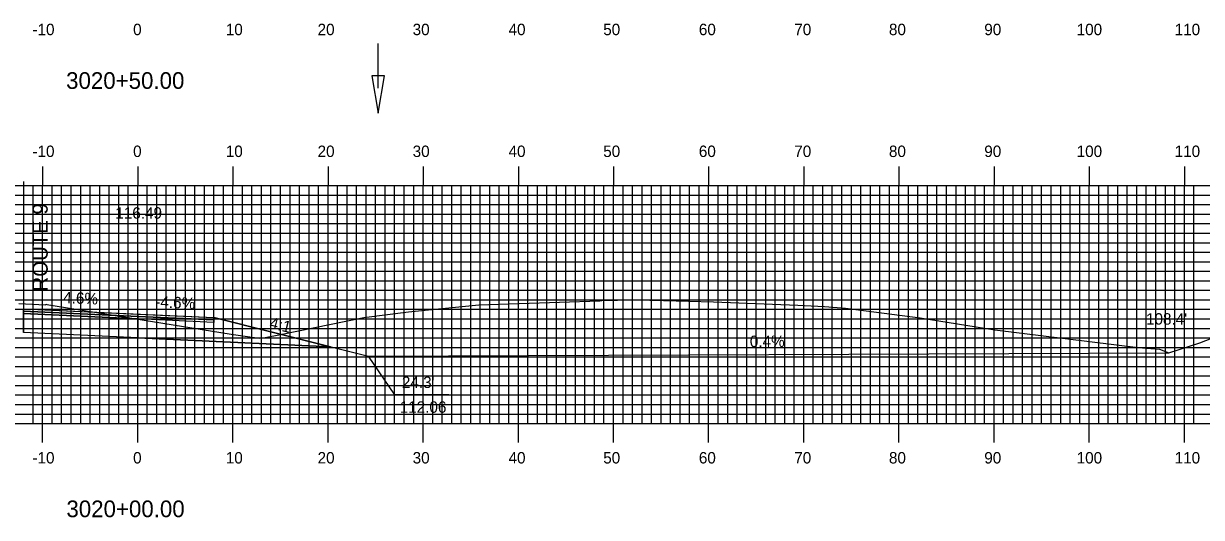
# Model space of a CAD drawing. Extents: x 1685979 to 1686323, y 461260 to 461480.
# Drawn here: x 1686133.3 to 1686257.1, y 461358.2 to 461410.1 of the extents above; entities that cross this region are included whole.
import ezdxf

# ---------------------------------------------------------------- set-up
doc = ezdxf.new("R2010")
doc.units = 0
for name, color, linetype in [('ANNOTATION', 7, 'Continuous'), ('D_Drainage_Ditch_Line', 7, 'Continuous'), ('D_Roadway_Centerline_Text', 7, 'Continuous'), ('D_Roadway_Edge_Shoulder', 7, 'Continuous'), ('D_Roadway_Edge_TW', 7, 'Continuous'), ('D_Roadway_Pavement', 7, 'Continuous'), ('D_Roadway_SlopeLines', 7, 'Continuous'), ('D_Roadway_SubGrade', 7, 'Continuous'), ('D_Text_Standard', 7, 'Continuous'), ('H_V ANNOTATION', 7, 'Continuous'), ('M_Roadway_Centerline', 7, 'Continuous'), ('MAJOR', 7, 'Continuous'), ('MINOR', 7, 'Continuous'), ('S_Roadway_Centerline', 7, 'Continuous')]:
    doc.layers.add(name, color=color, linetype=linetype)

msp = doc.modelspace()

# ---------------------------------------------------------------- linework, layer by layer
at = {"layer": 'ANNOTATION'}
msp.add_lwpolyline([(1686177.97, 461371.08), (1686172.28, 461371.08), (1686169.51, 461375.13)], dxfattribs=at)
at = {"layer": 'D_Drainage_Ditch_Line'}
msp.add_line((1686170.53, 461403.29), (1686170.53, 461407.99), dxfattribs=at)
msp.add_lwpolyline([(1686171.18, 461404.6), (1686169.87, 461404.6), (1686170.53, 461400.66)], close=True, dxfattribs=at)
at = {"layer": 'D_Roadway_Edge_Shoulder'}
for points in [[(1686133.26, 461379.87), (1686133.26, 461380.12), (1686153.26, 461379.2), (1686153.26, 461378.95), (1686145.26, 461379.31)], [(1686145.26, 461379.56), (1686153.26, 461379.2), (1686153.26, 461378.95), (1686145.26, 461379.31)], [(1686145.26, 461379.56), (1686153.26, 461379.2), (1686153.26, 461378.95), (1686145.26, 461379.31)], [(1686145.26, 461379.56), (1686153.26, 461379.2), (1686153.26, 461378.95), (1686145.26, 461379.31)], [(1686145.26, 461379.31), (1686153.26, 461378.95), (1686153.26, 461378.7), (1686145.26, 461379.06)]]:
    msp.add_lwpolyline(points, close=True, dxfattribs=at)
at = {"layer": 'D_Roadway_Edge_TW'}
msp.add_lwpolyline([(1686133.26, 461380.12), (1686145.26, 461379.56), (1686145.26, 461379.31), (1686133.26, 461379.87)], close=True, dxfattribs=at)
msp.add_lwpolyline([(1686133.26, 461380.12), (1686145.26, 461379.56), (1686145.26, 461379.31), (1686133.26, 461379.87)], close=True, dxfattribs=at)
msp.add_lwpolyline([(1686133.26, 461380.12), (1686145.26, 461379.56), (1686145.26, 461379.31), (1686133.26, 461379.87)], close=True, dxfattribs=at)
for points in [[(1686133.26, 461380.12), (1686133.26, 461379.87)], [(1686145.26, 461379.31), (1686145.26, 461379.56)]]:
    msp.add_lwpolyline(points, dxfattribs=at)
at = {"layer": 'D_Roadway_Pavement'}
msp.add_lwpolyline([(1686133.26, 461379.87), (1686145.26, 461379.31), (1686145.26, 461379.06), (1686133.26, 461379.62)], close=True, dxfattribs=at)
msp.add_lwpolyline([(1686133.26, 461379.87), (1686145.26, 461379.31), (1686145.26, 461379.06), (1686133.26, 461379.62)], close=True, dxfattribs=at)
msp.add_lwpolyline([(1686133.26, 461379.87), (1686145.26, 461379.31), (1686145.26, 461379.06), (1686133.26, 461379.62)], close=True, dxfattribs=at)
msp.add_lwpolyline([(1686133.26, 461379.87), (1686145.26, 461379.31), (1686145.26, 461379.06), (1686133.26, 461379.62)], close=True, dxfattribs=at)
msp.add_lwpolyline([(1686133.26, 461379.87), (1686145.26, 461379.31), (1686145.26, 461379.06), (1686133.26, 461379.62)], close=True, dxfattribs=at)
for points in [[(1686133.26, 461379.87), (1686133.26, 461379.62)], [(1686145.26, 461379.31), (1686145.26, 461379.06)], [(1686145.26, 461379.31), (1686145.26, 461379.06)], [(1686145.26, 461379.31), (1686145.26, 461379.06)], [(1686145.26, 461379.31), (1686145.26, 461379.06)], [(1686145.26, 461379.31), (1686145.26, 461379.06)], [(1686145.26, 461379.31), (1686145.26, 461379.06)], [(1686145.26, 461379.06), (1686145.26, 461379.31)], [(1686145.26, 461379.31), (1686145.26, 461379.06)]]:
    msp.add_lwpolyline(points, dxfattribs=at)
at = {"layer": 'D_Roadway_SlopeLines'}
for points in [[(1686153.26, 461379.2), (1686169.51, 461375.13)], [(1686153.26, 461379.2), (1686169.51, 461375.13)], [(1686153.26, 461379.2), (1686169.51, 461375.13)], [(1686153.26, 461379.2), (1686169.51, 461375.13)], [(1686169.51, 461375.13), (1686253.62, 461375.48)], [(1686169.51, 461375.13), (1686253.62, 461375.48)], [(1686169.51, 461375.13), (1686253.62, 461375.48)], [(1686169.51, 461375.13), (1686253.62, 461375.48)]]:
    msp.add_lwpolyline(points, dxfattribs=at)
at = {"layer": 'D_Roadway_SubGrade'}
msp.add_line((1686133.26, 461393.49), (1686133.26, 461377.62), dxfattribs=at)
msp.add_lwpolyline([(1686133.26, 461379.62), (1686133.26, 461377.62)], dxfattribs=at)
msp.add_lwpolyline([(1686133.26, 461379.62), (1686133.26, 461377.62)], dxfattribs=at)
for points in [[(1686133.26, 461379.62), (1686145.26, 461379.06), (1686145.26, 461377.06), (1686133.26, 461377.62)], [(1686133.26, 461379.62), (1686145.26, 461379.06), (1686145.26, 461377.06), (1686133.26, 461377.62)], [(1686133.26, 461379.62), (1686145.26, 461379.06), (1686145.26, 461377.06), (1686133.26, 461377.62)], [(1686145.26, 461377.06), (1686165.51, 461376.13), (1686153.26, 461379.2), (1686153.26, 461378.95), (1686145.26, 461379.31), (1686145.26, 461379.06)], [(1686145.26, 461379.06), (1686145.26, 461379.31), (1686153.26, 461378.95), (1686153.26, 461379.2), (1686165.51, 461376.13), (1686145.26, 461377.06)], [(1686145.26, 461379.06), (1686145.26, 461379.31), (1686153.26, 461378.95), (1686153.26, 461379.2), (1686165.51, 461376.13), (1686145.26, 461377.06)], [(1686145.26, 461377.06), (1686165.51, 461376.13), (1686153.26, 461379.2), (1686153.26, 461378.95), (1686145.26, 461379.31), (1686145.26, 461379.06)]]:
    msp.add_lwpolyline(points, close=True, dxfattribs=at)
at = {"layer": 'MAJOR'}
for p, q in [((1686135.26, 461395.08), (1686135.26, 461393.07)), ((1686145.26, 461395.08), (1686145.26, 461393.07)), ((1686155.26, 461395.08), (1686155.26, 461393.07)), ((1686165.26, 461395.08), (1686165.26, 461393.07)), ((1686175.26, 461395.08), (1686175.26, 461393.07)), ((1686185.26, 461395.08), (1686185.26, 461393.07)), ((1686195.26, 461395.08), (1686195.26, 461393.07)), ((1686205.26, 461395.08), (1686205.26, 461393.07)), ((1686215.26, 461395.08), (1686215.26, 461393.07)), ((1686225.26, 461395.08), (1686225.26, 461393.07)), ((1686235.26, 461395.08), (1686235.26, 461393.07)), ((1686245.26, 461395.08), (1686245.26, 461393.07)), ((1686255.26, 461395.08), (1686255.26, 461393.07)), ((1686005.26, 461393.07), (1686285.26, 461393.07)), ((1686005.26, 461393.07), (1686285.26, 461393.07)), ((1686135.26, 461368.07), (1686135.26, 461393.07)), ((1686145.26, 461368.07), (1686145.26, 461393.07)), ((1686155.26, 461368.07), (1686155.26, 461393.07)), ((1686165.26, 461368.07), (1686165.26, 461393.07)), ((1686175.26, 461368.07), (1686175.26, 461393.07)), ((1686185.26, 461368.07), (1686185.26, 461393.07)), ((1686195.26, 461368.07), (1686195.26, 461393.07)), ((1686205.26, 461368.07), (1686205.26, 461393.07)), ((1686215.26, 461368.07), (1686215.26, 461393.07)), ((1686225.26, 461368.07), (1686225.26, 461393.07)), ((1686235.26, 461368.07), (1686235.26, 461393.07)), ((1686245.26, 461368.07), (1686245.26, 461393.07)), ((1686255.26, 461368.07), (1686255.26, 461393.07)), ((1686005.26, 461388.07), (1686285.26, 461388.07)), ((1686005.26, 461383.07), (1686285.26, 461383.07)), ((1686005.26, 461378.07), (1686285.26, 461378.07)), ((1686005.26, 461373.07), (1686285.26, 461373.07)), ((1686005.26, 461368.07), (1686285.26, 461368.07)), ((1686005.26, 461368.07), (1686285.26, 461368.07)), ((1686135.26, 461366.07), (1686135.26, 461368.07)), ((1686145.26, 461366.07), (1686145.26, 461368.07)), ((1686155.26, 461366.07), (1686155.26, 461368.07)), ((1686165.26, 461366.07), (1686165.26, 461368.07)), ((1686175.26, 461366.07), (1686175.26, 461368.07)), ((1686185.26, 461366.07), (1686185.26, 461368.07)), ((1686195.26, 461366.07), (1686195.26, 461368.07)), ((1686205.26, 461366.07), (1686205.26, 461368.07)), ((1686215.26, 461366.07), (1686215.26, 461368.07)), ((1686225.26, 461366.07), (1686225.26, 461368.07)), ((1686235.26, 461366.07), (1686235.26, 461368.07)), ((1686245.26, 461366.07), (1686245.26, 461368.07)), ((1686255.26, 461366.07), (1686255.26, 461368.07))]:
    msp.add_line(p, q, dxfattribs=at)
at = {"layer": 'MINOR'}
for p, q in [((1686134.26, 461368.07), (1686134.26, 461393.07)), ((1686136.26, 461368.07), (1686136.26, 461393.07)), ((1686137.26, 461368.07), (1686137.26, 461393.07)), ((1686138.26, 461368.07), (1686138.26, 461393.07)), ((1686139.26, 461368.07), (1686139.26, 461393.07)), ((1686140.26, 461368.07), (1686140.26, 461393.07)), ((1686141.26, 461368.07), (1686141.26, 461393.07)), ((1686142.26, 461368.07), (1686142.26, 461393.07)), ((1686143.26, 461368.07), (1686143.26, 461393.07)), ((1686144.26, 461368.07), (1686144.26, 461393.07)), ((1686146.26, 461368.07), (1686146.26, 461393.07)), ((1686147.26, 461368.07), (1686147.26, 461393.07)), ((1686148.26, 461368.07), (1686148.26, 461393.07)), ((1686149.26, 461368.07), (1686149.26, 461393.07)), ((1686150.26, 461368.07), (1686150.26, 461393.07)), ((1686151.26, 461368.07), (1686151.26, 461393.07)), ((1686152.26, 461368.07), (1686152.26, 461393.07)), ((1686153.26, 461368.07), (1686153.26, 461393.07)), ((1686154.26, 461368.07), (1686154.26, 461393.07)), ((1686156.26, 461368.07), (1686156.26, 461393.07)), ((1686157.26, 461368.07), (1686157.26, 461393.07)), ((1686158.26, 461368.07), (1686158.26, 461393.07)), ((1686159.26, 461368.07), (1686159.26, 461393.07)), ((1686160.26, 461368.07), (1686160.26, 461393.07)), ((1686161.26, 461368.07), (1686161.26, 461393.07)), ((1686162.26, 461368.07), (1686162.26, 461393.07)), ((1686163.26, 461368.07), (1686163.26, 461393.07)), ((1686164.26, 461368.07), (1686164.26, 461393.07)), ((1686166.26, 461368.07), (1686166.26, 461393.07)), ((1686167.26, 461368.07), (1686167.26, 461393.07)), ((1686168.26, 461368.07), (1686168.26, 461393.07)), ((1686169.26, 461368.07), (1686169.26, 461393.07)), ((1686170.26, 461368.07), (1686170.26, 461393.07)), ((1686171.26, 461368.07), (1686171.26, 461393.07)), ((1686172.26, 461368.07), (1686172.26, 461393.07)), ((1686173.26, 461368.07), (1686173.26, 461393.07)), ((1686174.26, 461368.07), (1686174.26, 461393.07)), ((1686176.26, 461368.07), (1686176.26, 461393.07)), ((1686177.26, 461368.07), (1686177.26, 461393.07)), ((1686178.26, 461368.07), (1686178.26, 461393.07)), ((1686179.26, 461368.07), (1686179.26, 461393.07)), ((1686180.26, 461368.07), (1686180.26, 461393.07)), ((1686181.26, 461368.07), (1686181.26, 461393.07)), ((1686182.26, 461368.07), (1686182.26, 461393.07)), ((1686183.26, 461368.07), (1686183.26, 461393.07)), ((1686184.26, 461368.07), (1686184.26, 461393.07)), ((1686186.26, 461368.07), (1686186.26, 461393.07)), ((1686187.26, 461368.07), (1686187.26, 461393.07)), ((1686188.26, 461368.07), (1686188.26, 461393.07)), ((1686189.26, 461368.07), (1686189.26, 461393.07)), ((1686190.26, 461368.07), (1686190.26, 461393.07)), ((1686191.26, 461368.07), (1686191.26, 461393.07)), ((1686192.26, 461368.07), (1686192.26, 461393.07)), ((1686193.26, 461368.07), (1686193.26, 461393.07)), ((1686194.26, 461368.07), (1686194.26, 461393.07)), ((1686196.26, 461368.07), (1686196.26, 461393.07)), ((1686197.26, 461368.07), (1686197.26, 461393.07)), ((1686198.26, 461368.07), (1686198.26, 461393.07)), ((1686199.26, 461368.07), (1686199.26, 461393.07)), ((1686200.26, 461368.07), (1686200.26, 461393.07)), ((1686201.26, 461368.07), (1686201.26, 461393.07)), ((1686202.26, 461368.07), (1686202.26, 461393.07)), ((1686203.26, 461368.07), (1686203.26, 461393.07)), ((1686204.26, 461368.07), (1686204.26, 461393.07)), ((1686206.26, 461368.07), (1686206.26, 461393.07)), ((1686207.26, 461368.07), (1686207.26, 461393.07)), ((1686208.26, 461368.07), (1686208.26, 461393.07)), ((1686209.26, 461368.07), (1686209.26, 461393.07)), ((1686210.26, 461368.07), (1686210.26, 461393.07)), ((1686211.26, 461368.07), (1686211.26, 461393.07)), ((1686212.26, 461368.07), (1686212.26, 461393.07)), ((1686213.26, 461368.07), (1686213.26, 461393.07)), ((1686214.26, 461368.07), (1686214.26, 461393.07)), ((1686216.26, 461368.07), (1686216.26, 461393.07)), ((1686217.26, 461368.07), (1686217.26, 461393.07)), ((1686218.26, 461368.07), (1686218.26, 461393.07)), ((1686219.26, 461368.07), (1686219.26, 461393.07)), ((1686220.26, 461368.07), (1686220.26, 461393.07)), ((1686221.26, 461368.07), (1686221.26, 461393.07)), ((1686222.26, 461368.07), (1686222.26, 461393.07)), ((1686223.26, 461368.07), (1686223.26, 461393.07)), ((1686224.26, 461368.07), (1686224.26, 461393.07)), ((1686226.26, 461368.07), (1686226.26, 461393.07)), ((1686227.26, 461368.07), (1686227.26, 461393.07)), ((1686228.26, 461368.07), (1686228.26, 461393.07)), ((1686229.26, 461368.07), (1686229.26, 461393.07)), ((1686230.26, 461368.07), (1686230.26, 461393.07)), ((1686231.26, 461368.07), (1686231.26, 461393.07)), ((1686232.26, 461368.07), (1686232.26, 461393.07)), ((1686233.26, 461368.07), (1686233.26, 461393.07)), ((1686234.26, 461368.07), (1686234.26, 461393.07)), ((1686236.26, 461368.07), (1686236.26, 461393.07)), ((1686237.26, 461368.07), (1686237.26, 461393.07)), ((1686238.26, 461368.07), (1686238.26, 461393.07)), ((1686239.26, 461368.07), (1686239.26, 461393.07)), ((1686240.26, 461368.07), (1686240.26, 461393.07)), ((1686241.26, 461368.07), (1686241.26, 461393.07)), ((1686242.26, 461368.07), (1686242.26, 461393.07)), ((1686243.26, 461368.07), (1686243.26, 461393.07)), ((1686244.26, 461368.07), (1686244.26, 461393.07)), ((1686246.26, 461368.07), (1686246.26, 461393.07)), ((1686247.26, 461368.07), (1686247.26, 461393.07)), ((1686248.26, 461368.07), (1686248.26, 461393.07)), ((1686249.26, 461368.07), (1686249.26, 461393.07)), ((1686250.26, 461368.07), (1686250.26, 461393.07)), ((1686251.26, 461368.07), (1686251.26, 461393.07)), ((1686252.26, 461368.07), (1686252.26, 461393.07)), ((1686253.26, 461368.07), (1686253.26, 461393.07)), ((1686254.26, 461368.07), (1686254.26, 461393.07)), ((1686256.26, 461368.07), (1686256.26, 461393.07)), ((1686005.26, 461392.07), (1686285.26, 461392.07)), ((1686005.26, 461391.07), (1686285.26, 461391.07)), ((1686005.26, 461390.07), (1686285.26, 461390.07)), ((1686005.26, 461389.07), (1686285.26, 461389.07)), ((1686005.26, 461387.07), (1686285.26, 461387.07)), ((1686005.26, 461386.07), (1686285.26, 461386.07)), ((1686005.26, 461385.07), (1686285.26, 461385.07)), ((1686005.26, 461384.07), (1686285.26, 461384.07)), ((1686005.26, 461382.07), (1686285.26, 461382.07)), ((1686005.26, 461381.07), (1686285.26, 461381.07)), ((1686005.26, 461380.07), (1686285.26, 461380.07)), ((1686005.26, 461379.07), (1686285.26, 461379.07)), ((1686005.26, 461377.07), (1686285.26, 461377.07)), ((1686005.26, 461376.07), (1686285.26, 461376.07)), ((1686005.26, 461375.07), (1686285.26, 461375.07)), ((1686005.26, 461374.07), (1686285.26, 461374.07)), ((1686005.26, 461372.07), (1686285.26, 461372.07)), ((1686005.26, 461371.07), (1686285.26, 461371.07)), ((1686005.26, 461370.07), (1686285.26, 461370.07)), ((1686005.26, 461369.07), (1686285.26, 461369.07))]:
    msp.add_line(p, q, dxfattribs=at)
at = {"layer": 'S_Roadway_Centerline'}
msp.add_lwpolyline([(1686132.77, 461380.68), (1686135.57, 461380.55), (1686135.59, 461380.61), (1686135.6, 461380.61), (1686135.71, 461380.59), (1686155.07, 461377.46), (1686158.02, 461377.04), (1686158.48, 461377.09), (1686160.25, 461377.41), (1686169.03, 461379.21), (1686173.72, 461379.82), (1686181.11, 461380.54), (1686181.11, 461380.54), (1686181.12, 461380.55), (1686193.81, 461380.97), (1686194.04, 461380.98), (1686197.32, 461381.07), (1686197.65, 461381.05), (1686200.53, 461380.98), (1686205.77, 461380.85), (1686214.62, 461380.5), (1686217.44, 461380.36), (1686219.64, 461380.19), (1686227.48, 461379.19), (1686235.33, 461377.9), (1686250.41, 461376.07), (1686252.63, 461375.87), (1686253.61, 461375.48), (1686256.89, 461376.53), (1686263.48, 461379.09)], dxfattribs=at)

# ---------------------------------------------------------------- texts
at = {"layer": 'ANNOTATION'}
for s, height, rotation, p in [('ROUTE 9', 1.6, 90, (1686135.79, 461381.94)), ('4.6%', 1.2, 357.3662, (1686137.4, 461380.73)), ('-4.6%', 1.2, 357.3663, (1686147.08, 461380.28)), ('4:1', 1.2, 345.9638, (1686159.03, 461378.12)), ('0.4%', 1.2, 0.2398, (1686209.59, 461376.1))]:
    msp.add_text(s, height=height, rotation=rotation, dxfattribs=at).set_placement(p)
for s, p in [("24.3' ", (1686173.02, 461371.8)), ('112.06', (1686172.79, 461369.2))]:
    msp.add_text(s, height=1.2, dxfattribs=at).set_placement(p)
at = {"layer": 'D_Roadway_Centerline_Text'}
msp.add_text('116.49', height=1.2, dxfattribs=at).set_placement((1686142.9, 461389.59))
at = {"layer": 'D_Text_Standard'}
msp.add_text("108.4'", height=1.2, dxfattribs=at).set_placement((1686251.23, 461378.46))
at = {"layer": 'H_V ANNOTATION'}
for s, height, p in [('-10', 1.2, (1686134.19, 461408.87)), ('0', 1.2, (1686144.77, 461408.87)), ('10', 1.2, (1686154.51, 461408.87)), ('20', 1.2, (1686164.16, 461408.87)), ('30', 1.2, (1686174.15, 461408.87)), ('40', 1.2, (1686184.23, 461408.87)), ('50', 1.2, (1686194.18, 461408.87)), ('60', 1.2, (1686204.23, 461408.87)), ('70', 1.2, (1686214.26, 461408.87)), ('80', 1.2, (1686224.21, 461408.87)), ('90', 1.2, (1686234.23, 461408.87)), ('100', 1.2, (1686243.94, 461408.87)), ('110', 1.2, (1686254.24, 461408.87)), ('3020+50.00', 1.75, (1686137.73, 461403.23)), ('-10', 1.2, (1686134.19, 461396.07)), ('0', 1.2, (1686144.77, 461396.07)), ('10', 1.2, (1686154.51, 461396.07)), ('20', 1.2, (1686164.16, 461396.07)), ('30', 1.2, (1686174.15, 461396.07)), ('40', 1.2, (1686184.23, 461396.07)), ('50', 1.2, (1686194.18, 461396.07)), ('60', 1.2, (1686204.23, 461396.07)), ('70', 1.2, (1686214.26, 461396.07)), ('80', 1.2, (1686224.21, 461396.07)), ('90', 1.2, (1686234.23, 461396.07)), ('100', 1.2, (1686243.94, 461396.07)), ('110', 1.2, (1686254.24, 461396.07)), ('-10', 1.2, (1686134.19, 461363.87)), ('0', 1.2, (1686144.77, 461363.87)), ('10', 1.2, (1686154.51, 461363.87)), ('20', 1.2, (1686164.16, 461363.87)), ('30', 1.2, (1686174.15, 461363.87)), ('40', 1.2, (1686184.23, 461363.87)), ('50', 1.2, (1686194.18, 461363.87)), ('60', 1.2, (1686204.23, 461363.87)), ('70', 1.2, (1686214.26, 461363.87)), ('80', 1.2, (1686224.21, 461363.87)), ('90', 1.2, (1686234.23, 461363.87)), ('100', 1.2, (1686243.94, 461363.87)), ('110', 1.2, (1686254.24, 461363.87)), ('3020+00.00', 1.75, (1686137.76, 461358.23))]:
    msp.add_text(s, height=height, dxfattribs=at).set_placement(p)
at = {"layer": 'M_Roadway_Centerline'}
for s, p in [('C', (1686197.32, 461381.07)), ('L', (1686197.32, 461381.06))]:
    msp.add_text(s, height=0.0146, dxfattribs=at).set_placement(p)

doc.saveas('drawing.dxf')
